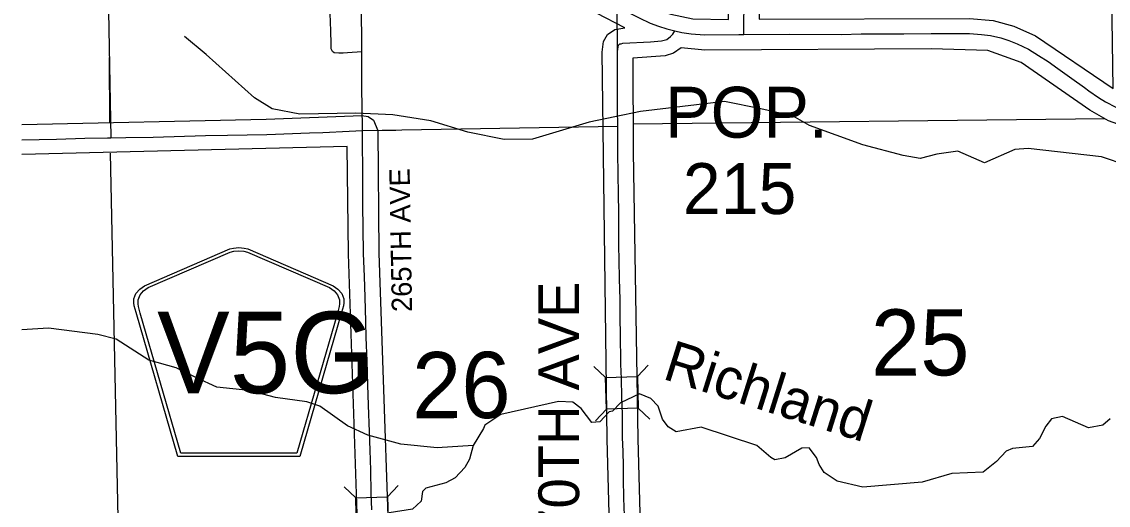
# Model space of a CAD drawing. Extents: x 10133 to 81668, y 7924 to 11018.
# Drawn here: x 10954.9 to 11275.1, y 9217.2 to 9359.7 of the extents above; entities that cross this region are included whole.
import ezdxf

# ---------------------------------------------------------------- set-up
doc = ezdxf.new("R2010")
doc.units = 0
for name, color, linetype in [('tdCoCityStreetMajor', 7, 'Continuous'), ('tdCoCityStreetMinor', 7, 'Continuous'), ('tdCoCorpPopTxt', 7, 'Continuous'), ('tdCoCorpTxt', 7, 'Continuous'), ('tdCoHydroRiver', 7, 'Continuous'), ('tdCoPriNonDiv', 7, 'Continuous'), ('tdCoRROwnerTxt', 7, 'Continuous'), ('tdCoSecRteBand', 7, 'Continuous'), ('tdCoSectNmbr', 7, 'Continuous'), ('tdCoShieldCoRte', 7, 'Continuous'), ('tdCoShieldStRte', 7, 'Continuous'), ('tdCoStrucNonDivPri', 7, 'Continuous'), ('tdCoSurfEarth', 7, 'Continuous'), ('tdCoSurfGravel', 7, 'Continuous'), ('tdCoUnicrpTwnTxt', 7, 'Continuous')]:
    doc.layers.add(name, color=color, linetype=linetype)

msp = doc.modelspace()

# ---------------------------------------------------------------- linework, layer by layer
at = {"layer": 'tdCoCityStreetMajor'}
for points in [[(11167.68, 9355.9), (11167.68, 9356.85), (11167.73, 9366.66), (11167.65, 9376.13), (11167.41, 9386.27), (11167.11, 9399.66), (11166.94, 9410.44), (11167.14, 9438.38), (11166.74, 9448.29), (11166.62, 9459.39), (11166.32, 9471.28), (11165.98, 9480.62), (11165.83, 9482.89), (11165.78, 9493.67), (11165.88, 9498.77), (11165.63, 9506.44), (11165.46, 9516.13), (11165.34, 9517.98), (11165.32, 9522.55)], [(11132.51, 9214.19), (11132.34, 9219.25), (11132.26, 9224.95), (11132.22, 9229.34), (11131.97, 9235.67), (11131.89, 9236.61), (11131.94, 9243.96), (11131.77, 9249.19), (11131.62, 9254.49), (11131.45, 9258.76), (11131.43, 9260.29), (11131.35, 9266.57), (11131.23, 9273.31), (11131.28, 9277.82), (11131.06, 9283.89), (11130.93, 9289.46), (11130.88, 9293.75), (11130.88, 9298.34), (11130.83, 9301.61)]]:
    msp.add_lwpolyline(points, dxfattribs=at)
at = {"layer": 'tdCoCityStreetMinor'}
for points in [[(11130.34, 9364.07), (11131.03, 9363.71), (11131.37, 9363.54), (11133.32, 9362.55), (11136.8, 9360.82), (11140.1, 9359.22), (11142.54, 9358.33), (11144.99, 9357.57), (11147.31, 9356.98)], [(11130.83, 9301.61), (11130.81, 9303.22), (11130.71, 9309.06), (11130.69, 9314.51), (11130.56, 9321.27), (11130.54, 9327.9), (11130.52, 9328.91), (11130.52, 9328.92), (11130.44, 9334.05), (11130.42, 9339.47), (11130.44, 9345.56), (11130.46, 9350.72), (11130.46, 9350.72), (11130.54, 9351.73), (11130.71, 9352.76), (11131.18, 9353.11), (11131.51, 9353.2), (11131.99, 9353.33), (11140.21, 9353.7), (11143.46, 9354.02), (11144.99, 9354.46), (11146.1, 9355.28), (11146.72, 9356.02), (11147.31, 9356.98)], [(11147.31, 9356.98), (11149.4, 9356.51), (11152.14, 9356.09), (11156.11, 9355.77), (11166.19, 9355.89), (11167.68, 9355.9), (11181.11, 9356.01), (11196.48, 9355.94), (11202.22, 9356.11), (11214.87, 9356.14), (11222.84, 9356.19), (11234.13, 9356.16), (11237.73, 9355.94), (11240.4, 9355.6), (11243.38, 9354.93), (11245.75, 9354.12), (11248.24, 9353.13), (11251.52, 9351.58), (11254.48, 9349.75), (11257.34, 9347.95), (11260.2, 9345.9), (11264.32, 9342.94), (11268.04, 9340.26), (11269.37, 9339.32), (11272.23, 9337.35), (11274.26, 9336.06), (11277.26, 9334.49)], [(10954.88, 9324.82), (10965.13, 9325.09), (10973.49, 9325.32), (10980.19, 9325.44), (10981.1, 9325.46), (10985.57, 9325.54), (10993.61, 9325.69), (11009.05, 9326.13), (11015.56, 9326.25), (11027.08, 9326.48), (11039.73, 9326.9), (11043.65, 9327.04), (11051.37, 9327.44), (11055.31, 9327.59)]]:
    msp.add_lwpolyline(points, dxfattribs=at)
at = {"layer": 'tdCoCorpPopTxt'}
msp.add_lwpolyline([(11055.1, 9350.75), (11050.91, 9350.52), (11049.6, 9350.45), (11048.29, 9350.42), (11046.97, 9350.51), (11046.49, 9350.88), (11046.08, 9351.69), (11046.03, 9353.17), (11045.93, 9356.97), (11045.81, 9362.12), (11045.79, 9363.05)], dxfattribs=at)
at = {"layer": 'tdCoHydroRiver'}
for points in [[(11295.73, 9312.17), (11273.1, 9319.84), (11251.51, 9322.32), (11247.49, 9322.01), (11238.56, 9318.07), (11230.69, 9321.49), (11224.55, 9320.68), (11219.59, 9319.41), (11214.61, 9320.28), (11202.72, 9323.39), (11186.99, 9329.05), (11182.21, 9331.81), (11172.7, 9334.02), (11162.01, 9336.21), (11137.2, 9333.18), (11122.09, 9330.09), (11105.37, 9325.07), (11097.08, 9324.93), (11086.39, 9327.12), (11075.44, 9330.49), (11064.28, 9332.2), (11053.38, 9332.73), (11036.81, 9332.45), (11028.73, 9333.97), (11023.47, 9337.2), (11009.28, 9349.98), (11002.8, 9355.32)], [(11087.94, 9234.8), (11077.29, 9234.15), (11066.62, 9235.15), (11056.87, 9237.83), (11050.9, 9240.57), (11042.75, 9246.35), (11038.94, 9247.71), (11029.68, 9248.98), (11021.84, 9250.97), (11012.35, 9252), (11006.38, 9254.74), (11000.41, 9257.72), (10992.32, 9259.95), (10982.75, 9266.18), (10977.28, 9267.51), (10962.8, 9269.4), (10954.88, 9268.9)], [(11275.58, 9242.68), (11273.48, 9240.75), (11269.23, 9239.97), (11261.6, 9243.39), (11258.3, 9242.63), (11256.68, 9240.47), (11254.84, 9236.89), (11252.75, 9234.49), (11246.84, 9233.91), (11244.96, 9233.17), (11242.17, 9230.05), (11238.2, 9226.9), (11228.97, 9226.51), (11220.25, 9223.99), (11202.75, 9222.52), (11195.14, 9224.28), (11191.31, 9226.82), (11189.85, 9229.17), (11189.11, 9231.29), (11186.93, 9234.09), (11184.8, 9234.06), (11179.87, 9231.13), (11176.8, 9230.61), (11175.61, 9231.3), (11171.53, 9234.78), (11155.1, 9240.19), (11147.78, 9238.88), (11145.39, 9240.26), (11143.69, 9242.6), (11142.44, 9246.37), (11140.27, 9248.7), (11136.93, 9250.06), (11131.3, 9247.37), (11128.97, 9244.96), (11128.03, 9244.71), (11125.23, 9241.82), (11122.87, 9241.54), (11119.72, 9245.75), (11117.32, 9247.6), (11113.06, 9247.77), (11096.07, 9243.93), (11091.39, 9240.78), (11090.93, 9239.82), (11087.94, 9234.8)], [(11087.94, 9234.8), (11086.82, 9230.75), (11085.44, 9228.36), (11082.65, 9225.24), (11079.83, 9223.77), (11073.94, 9222.25), (11073.01, 9221.29), (11072.58, 9218.44), (11070.02, 9216.03), (11063.17, 9214.96)]]:
    msp.add_lwpolyline(points, dxfattribs=at)
at = {"layer": 'tdCoPriNonDiv'}
for points in [[(11130.85, 9108.64), (11127.4, 9236.64), (11125.97, 9350.74), (11126.35, 9353.88), (11127.46, 9355.88), (11129.68, 9357.35), (11132.65, 9357.86), (11124.27, 9362.2), (11128.47, 9370.15), (11141.86, 9363.37), (11146.21, 9361.9), (11152.66, 9360.56), (11163.2, 9360.35), (11162.44, 9410.37), (11162.64, 9438.3), (11161.33, 9482.87), (11160.45, 9548.03), (11058.16, 9546.07), (11058.02, 9471.43), (11049.02, 9471.47), (11048.94, 9571.48), (11048.48, 9594.91)], [(11276.48, 9339.98), (11276.18, 9360.35), (11274.35, 9454.39), (11272.65, 9480.82), (11273.29, 9500.68), (11272.49, 9550.2), (11169.45, 9548.19), (11170.33, 9483.05), (11171.63, 9438.35), (11171.44, 9410.46), (11172.19, 9360.44), (11234.14, 9360.66), (11241.18, 9360.03), (11247.21, 9358.37), (11253.67, 9355.53), (11276.48, 9339.98)], [(11445.46, 9211.77), (11445.79, 9217.23), (11447.66, 9222.11), (11445.89, 9226.32), (11445.66, 9229.24), (11447.41, 9333.75), (11361.24, 9330.3), (11290.22, 9326.46), (11283.1, 9327.63), (11275.18, 9330.5), (11269.68, 9333.64), (11249.37, 9347.62), (11239.62, 9351.16), (11222.85, 9351.69), (11156.16, 9351.27), (11149.17, 9351.99), (11146.98, 9350.43), (11144.45, 9349.63), (11134.95, 9348.96), (11135.06, 9321.32), (11136.39, 9236.77), (11139.85, 9108.74)], [(10954.88, 9329.4), (11026.96, 9330.97), (11055.14, 9332.08), (11057.01, 9331.75), (11058.57, 9330.68), (11059.81, 9327.57), (11060.13, 9291.52), (11064.1, 9173.84), (11055.11, 9173.41), (11051.14, 9291.25), (11050.79, 9322.9), (10954.88, 9320.53)]]:
    msp.add_lwpolyline(points, dxfattribs=at)
at = {"layer": 'tdCoSecRteBand'}
msp.add_lwpolyline([(11058.1, 9215.84), (11057.9, 9220.82), (11057.73, 9227.53), (11057.53, 9233.42), (11057.36, 9238.85), (11057.06, 9246.69), (11056.89, 9252.66), (11056.69, 9259.74), (11056.42, 9266.59), (11056.28, 9271.33), (11056.05, 9278.55), (11055.86, 9284.64), (11055.63, 9291.4), (11055.49, 9298.92), (11055.44, 9305.53), (11055.44, 9311.87), (11055.39, 9318.06), (11055.29, 9321.83), (11055.31, 9327.59)], dxfattribs=at)
at = {"layer": 'tdCoShieldCoRte'}
for points in [[(11123.52, 9258.11), (11126.92, 9254.88), (11136.31, 9255.14)], [(11139.46, 9258.48), (11136.31, 9255.14), (11136.57, 9245.76)], [(11123.96, 9242.09), (11127.19, 9245.5), (11126.92, 9254.88)], [(11139.98, 9242.54), (11136.57, 9245.76), (11127.19, 9245.5)], [(11049.89, 9222.64), (11053.31, 9219.42), (11062.69, 9219.7)], [(11065.84, 9223.04), (11062.69, 9219.7), (11062.96, 9210.32)], [(11050.36, 9206.63), (11053.58, 9210.04), (11053.31, 9219.42)]]:
    msp.add_lwpolyline(points, dxfattribs=at)
at = {"layer": 'tdCoStrucNonDivPri'}
for points in [[(10980.67, 9349.14), (10980.78, 9329.97)], [(11135.04, 9329.6), (11274.03, 9331.11)], [(11059.81, 9327.62), (11065.09, 9327.76)], [(10980.9, 9320.97), (10983.99, 9176.04)]]:
    msp.add_lwpolyline(points, dxfattribs=at)
at = {"layer": 'tdCoSurfEarth'}
msp.add_lwpolyline([(11055.31, 9327.59), (11055.31, 9328.98), (11055.24, 9333.79), (11055.14, 9340.77), (11055.14, 9347.26), (11055.1, 9350.75), (11055.07, 9354.24), (11055.09, 9355.47), (11055.04, 9360.94), (11055.06, 9363.47), (11055.07, 9365.28), (11055.07, 9367.7), (11055.01, 9372.92), (11054.99, 9374.53), (11054.94, 9381.44), (11054.94, 9382.53), (11054.92, 9385.23), (11054.82, 9388.34), (11054.86, 9389.67), (11054.86, 9389.67)], dxfattribs=at)
at = {"layer": 'tdCoSurfGravel'}
msp.add_lwpolyline([(11129.32, 9477.58), (11053.54, 9475.95), (10979.69, 9474.92), (10979.73, 9400.23), (10981.1, 9325.46), (10985.57, 9325.54), (10993.61, 9325.69), (11009.05, 9326.13), (11015.56, 9326.25), (11027.08, 9326.48), (11039.73, 9326.9), (11043.65, 9327.04), (11051.37, 9327.44), (11055.31, 9327.59), (11130.52, 9328.92), (11130.44, 9334.01), (11130.42, 9339.47), (11130.44, 9345.59), (11130.46, 9350.72), (11130.34, 9364.07)], close=True, dxfattribs=at)
at = {"layer": 'tdCoUnicrpTwnTxt'}
for points in [[(11000.9, 9231.59), (10988.61, 9274.02), (10988.03, 9275.99), (10987.92, 9276.87), (10987.92, 9278.05), (10988.55, 9279.59), (10989.64, 9280.87), (10991.08, 9281.87), (11016.17, 9292.72), (11017.3, 9292.97), (11018.86, 9293.1), (11020.43, 9292.97), (11021.55, 9292.72), (11046.65, 9281.87), (11048.08, 9280.87), (11049.17, 9279.59), (11049.81, 9278.05), (11049.81, 9276.87), (11049.7, 9275.99), (11049.12, 9274.02), (11036.83, 9231.59)], [(11001.78, 9232.53), (10989.82, 9273.83), (10989.26, 9275.72), (10989.15, 9276.57), (10989.15, 9277.69), (10989.77, 9279.18), (10990.81, 9280.4), (10992.19, 9281.36), (11016.28, 9291.78), (11017.36, 9292.02), (11018.86, 9292.15), (11020.36, 9292.02), (11021.45, 9291.78), (11045.53, 9281.36), (11046.91, 9280.4), (11047.96, 9279.18), (11048.57, 9277.69), (11048.57, 9276.57), (11048.47, 9275.72), (11047.91, 9273.83), (11035.95, 9232.53)]]:
    msp.add_lwpolyline(points, close=True, dxfattribs=at)

# ---------------------------------------------------------------- texts
at = {"layer": 'tdCoCorpTxt'}
msp.add_text('Richland', height=12, rotation=342.4575, dxfattribs=at).set_placement((11143.37, 9254.56))
at = {"layer": 'tdCoRROwnerTxt'}
for s, rotation, p in [('25', 0.2266, (11205.17, 9255.37)), ('26', 0.2259, (11069.96, 9242.81))]:
    msp.add_text(s, height=19.5, rotation=rotation, dxfattribs=at).set_placement(p)
at = {"layer": 'tdCoSectNmbr'}
for s, p in [('POP.', (11144.5, 9325.5)), ('215', (11149.69, 9303))]:
    msp.add_text(s, height=15, dxfattribs=at).set_placement(p)
at = {"layer": 'tdCoShieldStRte'}
for s, height, rotation, p in [('265TH AVE', 6, 91, (11069.93, 9274.19)), ('270TH AVE', 12, 90, (11119.14, 9198.39))]:
    msp.add_text(s, height=height, rotation=rotation, dxfattribs=at).set_placement(p)
at = {"layer": 'tdCoUnicrpTwnTxt'}
msp.add_text('V5G', height=24, dxfattribs=at).set_placement((10994.77, 9250.22))

doc.saveas('drawing.dxf')
